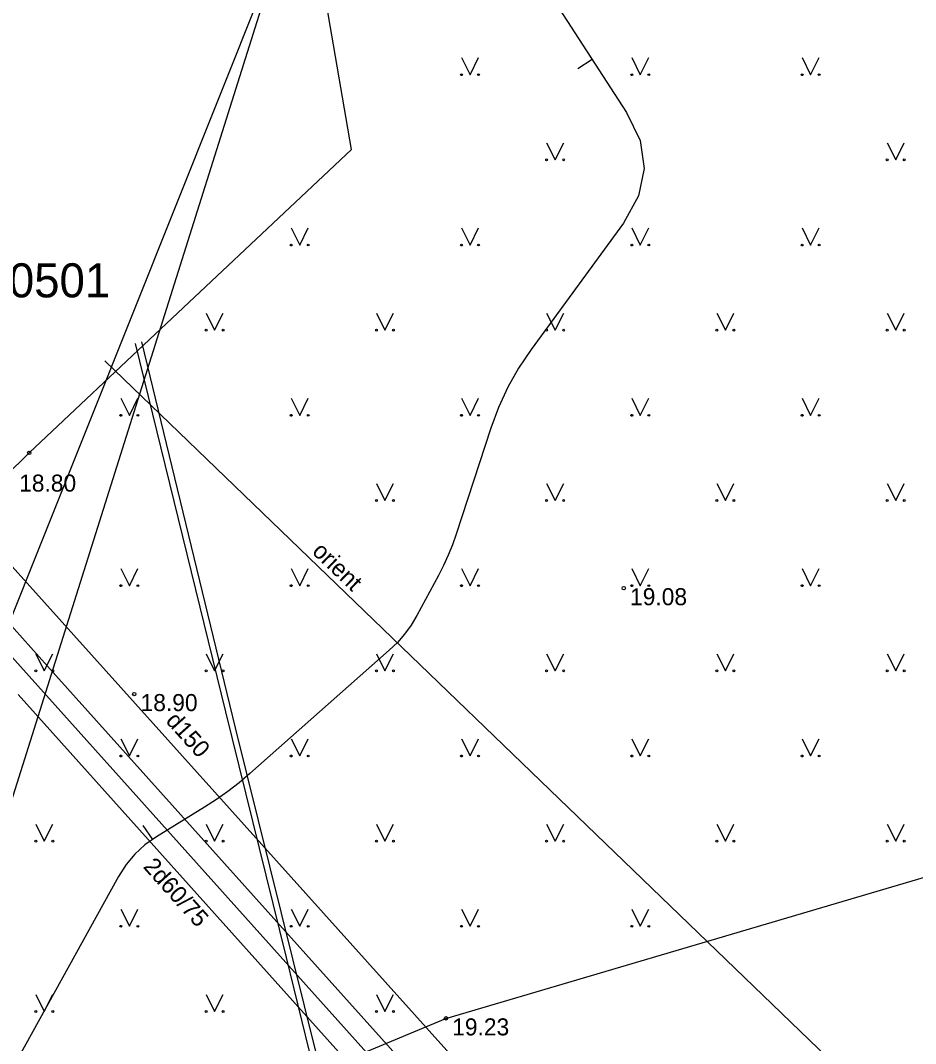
# Model space of a CAD drawing. Extents: x 532933 to 533143, y 328014 to 328163.
# Drawn here: x 532971.8 to 532998.08, y 328096.56 to 328126.59 of the extents above; entities that cross this region are included whole.
import ezdxf

# ---------------------------------------------------------------- set-up
doc = ezdxf.new("R2010")
doc.units = 0
for name, color, linetype in [('CELI_CMAL_####_####_#', 7, 'Continuous'), ('DREN_VADP_####_####_#', 7, 'Continuous'), ('DREN_VADP_####_TKST_#', 7, 'Continuous'), ('ELEK_VADP_ZSPR_####_#', 7, 'Continuous'), ('NORB_ZOGS_ZSTP_####_#', 7, 'Continuous'), ('RAMI_UZMR_####_####_#', 7, 'Continuous'), ('RELJ_AATZ_####_TKST_#', 7, 'Continuous'), ('RELJ_ELEM_####_####_#', 7, 'Continuous'), ('RELJ_HORZ_PAMT_####_#', 7, 'Continuous'), ('ROBZ_UZMR_####_####_#', 7, 'Continuous'), ('ROBZ_UZMR_####_TKST_#', 7, 'Continuous'), ('SILT_VADP_NEDR_####_#', 7, 'Continuous'), ('SILT_VADP_NEDR_TKST_#', 7, 'Continuous'), ('SILT_VADP_UDEN_TKAM_#', 7, 'Continuous'), ('TERT_ELEM_####_####_#', 7, 'Continuous'), ('UDTK_VADP_UDEN_####_#', 7, 'Continuous'), ('UDTK_VADP_UDEN_TKST_#', 7, 'Continuous')]:
    doc.layers.add(name, color=color, linetype=linetype)

msp = doc.modelspace()

# ---------------------------------------------------------------- linework, layer by layer
at = {"layer": 'CELI_CMAL_####_####_#'}
msp.add_lwpolyline([(532960.996, 328082.718), (532967.7, 328088.991), (532974.969, 328093.406), (532984.293, 328097.298), (532999.014, 328101.642), (533000, 328101.952)], dxfattribs=at)
at = {"layer": 'DREN_VADP_####_####_#'}
msp.add_line((532992.538, 328087.211), (532970.198, 328112.068), dxfattribs=at)
at = {"layer": 'ELEK_VADP_ZSPR_####_#'}
for points in [[(532975.169, 328117.107), (532977.825, 328106.296), (532979.6, 328099.088), (532980.956, 328093.565), (532981.761, 328089.629), (532987.457, 328081.608)], [(532987.598, 328081.755), (532981.948, 328089.71), (532981.784, 328090.509), (532981.151, 328093.609), (532978.113, 328105.828), (532975.361, 328117.154)]]:
    msp.add_lwpolyline(points, dxfattribs=at)
at = {"layer": 'NORB_ZOGS_ZSTP_####_#'}
for points in [[(532975.922, 328117.541), (532981.52, 328122.805), (532979.891, 328132.255)], [(532975.922, 328117.541), (532972.059, 328113.9), (532964.921, 328106.875)]]:
    msp.add_lwpolyline(points, dxfattribs=at)
at = {"layer": 'RAMI_UZMR_####_####_#'}
msp.add_lwpolyline([(532947.854, 328059.458), (532970.012, 328105.269), (532980.164, 328130.66), (532983.041, 328140.509), (533003.397, 328153.917), (533034.71, 328122.623), (533045.001, 328112.629), (533020.332, 328088.009), (533039.378, 328069.977), (533029.682, 328029.753), (533016.724, 328021.343), (532947.854, 328059.458)], dxfattribs=at)
at = {"layer": 'RELJ_ELEM_####_####_#'}
for centre in [(532972.059, 328113.9), (532989.514, 328109.926), (532975.142, 328106.818), (532984.292, 328097.298)]:
    msp.add_circle(centre, 0.05, dxfattribs=at)
at = {"layer": 'RELJ_HORZ_PAMT_####_#'}
for p, q in [((532988.162, 328125.186), (532988.582, 328125.457)), ((532975.393, 328102.959), (532975.681, 328102.551))]:
    msp.add_line(p, q, dxfattribs=at)
msp.add_lwpolyline([(532984.128, 328132.338), (532989.598, 328123.887), (532989.994, 328123.064), (532990.11, 328122.249), (532989.948, 328121.442), (532989.506, 328120.643), (532986.791, 328116.931), (532986.427, 328116.389), (532986.108, 328115.824), (532985.836, 328115.235), (532985.609, 328114.623), (532984.594, 328111.51), (532984.484, 328111.197), (532984.361, 328110.891), (532984.224, 328110.59), (532984.073, 328110.295), (532983.442, 328109.128), (532983.273, 328108.845), (532983.081, 328108.58), (532982.866, 328108.334), (532982.629, 328108.105), (532978.537, 328104.483), (532978.22, 328104.215), (532977.893, 328103.962), (532977.555, 328103.722), (532977.207, 328103.498), (532975.79, 328102.628), (532975.455, 328102.392), (532975.159, 328102.12), (532974.9, 328101.811), (532974.68, 328101.466), (532970.462, 328093.847)], dxfattribs=at)
at = {"layer": 'ROBZ_UZMR_####_####_#'}
msp.add_line((532984.275, 328144.093), (532962.791, 328075.982), dxfattribs=at)
at = {"layer": 'SILT_VADP_NEDR_####_#'}
msp.add_line((532971.8, 328107.627), (532967.413, 328112.519), dxfattribs=at)
msp.add_lwpolyline([(532988.748, 328088.729), (532971.8, 328107.627)], dxfattribs=at)
at = {"layer": 'SILT_VADP_UDEN_TKAM_#'}
msp.add_line((532972.841, 328107.364), (532967.679, 328113.121), dxfattribs=at)
for points in [[(532972.841, 328107.364), (532989.142, 328089.188)], [(532988.353, 328088.27), (532971.734, 328106.801)]]:
    msp.add_lwpolyline(points, dxfattribs=at)
at = {"layer": 'TERT_ELEM_####_####_#'}
for p, q in [((532984.75, 328125.5), (532985, 328125)), ((532985, 328125), (532985.25, 328125.5)), ((532989.75, 328125.5), (532990, 328125)), ((532990, 328125), (532990.25, 328125.5)), ((532994.75, 328125.5), (532995, 328125)), ((532995, 328125), (532995.25, 328125.5)), ((532987.25, 328123), (532987.5, 328122.5)), ((532987.5, 328122.5), (532987.75, 328123)), ((532997.25, 328123), (532997.5, 328122.5)), ((532997.5, 328122.5), (532997.75, 328123)), ((532979.75, 328120.5), (532980, 328120)), ((532980, 328120), (532980.25, 328120.5)), ((532984.75, 328120.5), (532985, 328120)), ((532985, 328120), (532985.25, 328120.5)), ((532989.75, 328120.5), (532990, 328120)), ((532990, 328120), (532990.25, 328120.5)), ((532994.75, 328120.5), (532995, 328120)), ((532995, 328120), (532995.25, 328120.5)), ((532977.25, 328118), (532977.5, 328117.5)), ((532977.5, 328117.5), (532977.75, 328118)), ((532982.25, 328118), (532982.5, 328117.5)), ((532982.5, 328117.5), (532982.75, 328118)), ((532987.25, 328118), (532987.5, 328117.5)), ((532987.5, 328117.5), (532987.75, 328118)), ((532992.25, 328118), (532992.5, 328117.5)), ((532992.5, 328117.5), (532992.75, 328118)), ((532997.25, 328118), (532997.5, 328117.5)), ((532997.5, 328117.5), (532997.75, 328118)), ((532974.75, 328115.5), (532975, 328115)), ((532975, 328115), (532975.25, 328115.5)), ((532979.75, 328115.5), (532980, 328115)), ((532980, 328115), (532980.25, 328115.5)), ((532984.75, 328115.5), (532985, 328115)), ((532985, 328115), (532985.25, 328115.5)), ((532989.75, 328115.5), (532990, 328115)), ((532990, 328115), (532990.25, 328115.5)), ((532994.75, 328115.5), (532995, 328115)), ((532995, 328115), (532995.25, 328115.5)), ((532982.25, 328113), (532982.5, 328112.5)), ((532982.5, 328112.5), (532982.75, 328113)), ((532987.25, 328113), (532987.5, 328112.5)), ((532987.5, 328112.5), (532987.75, 328113)), ((532992.25, 328113), (532992.5, 328112.5)), ((532992.5, 328112.5), (532992.75, 328113)), ((532997.25, 328113), (532997.5, 328112.5)), ((532997.5, 328112.5), (532997.75, 328113)), ((532974.75, 328110.5), (532975, 328110)), ((532975, 328110), (532975.25, 328110.5)), ((532979.75, 328110.5), (532980, 328110)), ((532980, 328110), (532980.25, 328110.5)), ((532984.75, 328110.5), (532985, 328110)), ((532985, 328110), (532985.25, 328110.5)), ((532989.75, 328110.5), (532990, 328110)), ((532990, 328110), (532990.25, 328110.5)), ((532994.75, 328110.5), (532995, 328110)), ((532995, 328110), (532995.25, 328110.5)), ((532972.25, 328108), (532972.5, 328107.5)), ((532972.5, 328107.5), (532972.75, 328108)), ((532977.25, 328108), (532977.5, 328107.5)), ((532977.5, 328107.5), (532977.75, 328108)), ((532982.25, 328108), (532982.5, 328107.5)), ((532982.5, 328107.5), (532982.75, 328108)), ((532987.25, 328108), (532987.5, 328107.5)), ((532987.5, 328107.5), (532987.75, 328108)), ((532992.25, 328108), (532992.5, 328107.5)), ((532992.5, 328107.5), (532992.75, 328108)), ((532997.25, 328108), (532997.5, 328107.5)), ((532997.5, 328107.5), (532997.75, 328108)), ((532974.75, 328105.5), (532975, 328105)), ((532975, 328105), (532975.25, 328105.5)), ((532979.75, 328105.5), (532980, 328105)), ((532980, 328105), (532980.25, 328105.5)), ((532984.75, 328105.5), (532985, 328105)), ((532985, 328105), (532985.25, 328105.5)), ((532989.75, 328105.5), (532990, 328105)), ((532990, 328105), (532990.25, 328105.5)), ((532994.75, 328105.5), (532995, 328105)), ((532995, 328105), (532995.25, 328105.5)), ((532972.25, 328103), (532972.5, 328102.5)), ((532972.5, 328102.5), (532972.75, 328103)), ((532977.25, 328103), (532977.5, 328102.5)), ((532977.5, 328102.5), (532977.75, 328103)), ((532982.25, 328103), (532982.5, 328102.5)), ((532982.5, 328102.5), (532982.75, 328103)), ((532987.25, 328103), (532987.5, 328102.5)), ((532987.5, 328102.5), (532987.75, 328103)), ((532992.25, 328103), (532992.5, 328102.5)), ((532992.5, 328102.5), (532992.75, 328103)), ((532997.25, 328103), (532997.5, 328102.5)), ((532997.5, 328102.5), (532997.75, 328103)), ((532974.75, 328100.5), (532975, 328100)), ((532975, 328100), (532975.25, 328100.5)), ((532979.75, 328100.5), (532980, 328100)), ((532980, 328100), (532980.25, 328100.5)), ((532984.75, 328100.5), (532985, 328100)), ((532985, 328100), (532985.25, 328100.5)), ((532989.75, 328100.5), (532990, 328100)), ((532990, 328100), (532990.25, 328100.5)), ((532972.25, 328098), (532972.5, 328097.5)), ((532972.5, 328097.5), (532972.75, 328098)), ((532977.25, 328098), (532977.5, 328097.5)), ((532977.5, 328097.5), (532977.75, 328098)), ((532982.25, 328098), (532982.5, 328097.5)), ((532982.5, 328097.5), (532982.75, 328098))]:
    msp.add_line(p, q, dxfattribs=at)
for centre, radius in [((532984.75, 328125), 0.028), ((532985.25, 328125), 0.0263), ((532989.75, 328125), 0.028), ((532990.25, 328125), 0.0263), ((532994.75, 328125), 0.028), ((532995.25, 328125), 0.0263), ((532987.25, 328122.5), 0.028), ((532987.75, 328122.5), 0.0263), ((532997.25, 328122.5), 0.028), ((532997.75, 328122.5), 0.0263), ((532979.75, 328120), 0.028), ((532980.25, 328120), 0.0263), ((532984.75, 328120), 0.028), ((532985.25, 328120), 0.0263), ((532989.75, 328120), 0.028), ((532990.25, 328120), 0.0263), ((532994.75, 328120), 0.028), ((532995.25, 328120), 0.0263), ((532977.25, 328117.5), 0.028), ((532977.75, 328117.5), 0.0263), ((532982.25, 328117.5), 0.028), ((532982.75, 328117.5), 0.0263), ((532987.25, 328117.5), 0.028), ((532987.75, 328117.5), 0.0263), ((532992.25, 328117.5), 0.028), ((532992.75, 328117.5), 0.0263), ((532997.25, 328117.5), 0.028), ((532997.75, 328117.5), 0.0263), ((532974.75, 328115), 0.028), ((532975.25, 328115), 0.0263), ((532979.75, 328115), 0.028), ((532980.25, 328115), 0.0263), ((532984.75, 328115), 0.028), ((532985.25, 328115), 0.0263), ((532989.75, 328115), 0.028), ((532990.25, 328115), 0.0263), ((532994.75, 328115), 0.028), ((532995.25, 328115), 0.0263), ((532982.25, 328112.5), 0.028), ((532982.75, 328112.5), 0.0263), ((532987.25, 328112.5), 0.028), ((532987.75, 328112.5), 0.0263), ((532992.25, 328112.5), 0.028), ((532992.75, 328112.5), 0.0263), ((532997.25, 328112.5), 0.028), ((532997.75, 328112.5), 0.0263), ((532974.75, 328110), 0.028), ((532975.25, 328110), 0.0263), ((532979.75, 328110), 0.028), ((532980.25, 328110), 0.0263), ((532984.75, 328110), 0.028), ((532985.25, 328110), 0.0263), ((532989.75, 328110), 0.028), ((532990.25, 328110), 0.0263), ((532994.75, 328110), 0.028), ((532995.25, 328110), 0.0263), ((532972.25, 328107.5), 0.028), ((532972.75, 328107.5), 0.0263), ((532977.25, 328107.5), 0.028), ((532977.75, 328107.5), 0.0263), ((532982.25, 328107.5), 0.028), ((532982.75, 328107.5), 0.0263), ((532987.25, 328107.5), 0.028), ((532987.75, 328107.5), 0.0263), ((532992.25, 328107.5), 0.028), ((532992.75, 328107.5), 0.0263), ((532997.25, 328107.5), 0.028), ((532997.75, 328107.5), 0.0263), ((532974.75, 328105), 0.028), ((532975.25, 328105), 0.0263), ((532979.75, 328105), 0.028), ((532980.25, 328105), 0.0263), ((532984.75, 328105), 0.028), ((532985.25, 328105), 0.0263), ((532989.75, 328105), 0.028), ((532990.25, 328105), 0.0263), ((532994.75, 328105), 0.028), ((532995.25, 328105), 0.0263), ((532972.25, 328102.5), 0.028), ((532972.75, 328102.5), 0.0263), ((532977.25, 328102.5), 0.028), ((532977.75, 328102.5), 0.0263), ((532982.25, 328102.5), 0.028), ((532982.75, 328102.5), 0.0263), ((532987.25, 328102.5), 0.028), ((532987.75, 328102.5), 0.0263), ((532992.25, 328102.5), 0.028), ((532992.75, 328102.5), 0.0263), ((532997.25, 328102.5), 0.028), ((532997.75, 328102.5), 0.0263), ((532974.75, 328100), 0.028), ((532975.25, 328100), 0.0263), ((532979.75, 328100), 0.028), ((532980.25, 328100), 0.0263), ((532984.75, 328100), 0.028), ((532985.25, 328100), 0.0263), ((532989.75, 328100), 0.028), ((532990.25, 328100), 0.0263), ((532972.25, 328097.5), 0.028), ((532972.75, 328097.5), 0.0263), ((532977.25, 328097.5), 0.028), ((532977.75, 328097.5), 0.0263), ((532982.25, 328097.5), 0.028), ((532982.75, 328097.5), 0.0263)]:
    msp.add_circle(centre, radius, dxfattribs=at)
at = {"layer": 'UDTK_VADP_UDEN_####_#'}
msp.add_line((533000, 328091.812), (532974.279, 328116.599), dxfattribs=at)

# ---------------------------------------------------------------- texts
at = {"layer": 'DREN_VADP_####_TKST_#'}
msp.add_text('d150', height=0.5, rotation=311.9476, dxfattribs=at).set_placement((532976.042, 328106.015))
at = {"layer": 'RELJ_AATZ_####_TKST_#'}
for s, p in [(' 18.80', (532971.576, 328112.761)), (' 19.08', (532989.514, 328109.426)), (' 18.90', (532975.142, 328106.318)), (' 19.23', (532984.292, 328096.798))]:
    msp.add_text(s, height=0.5, dxfattribs=at).set_placement(p)
at = {"layer": 'ROBZ_UZMR_####_TKST_#'}
msp.add_text('80170030501', height=1, dxfattribs=at).set_placement((532966.254, 328118.463))
at = {"layer": 'SILT_VADP_NEDR_TKST_#'}
msp.add_text('2d60/75', height=0.5, rotation=311.8861, dxfattribs=at).set_placement((532975.382, 328101.737))
at = {"layer": 'UDTK_VADP_UDEN_TKST_#'}
msp.add_text('orient', height=0.5, rotation=316.0591, dxfattribs=at).set_placement((532980.336, 328110.97))

doc.saveas('drawing.dxf')
